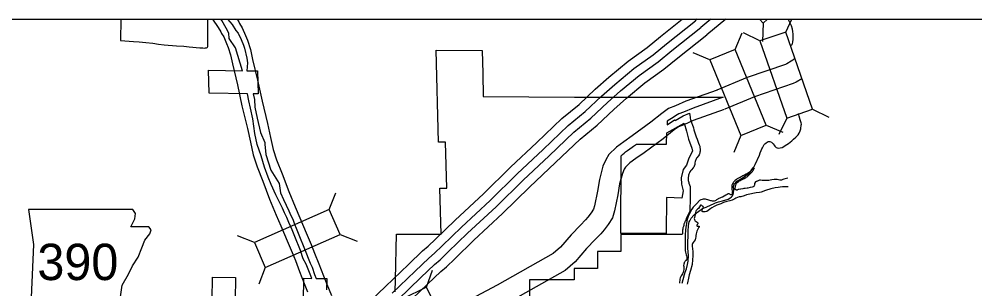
# Model space of a CAD drawing. Extents: x 813775 to 1157140, y 1757555 to 1979907.
# Drawn here: x 848124 to 875936, y 1960976 to 1968812 of the extents above; entities that cross this region are included whole.
import ezdxf

# ---------------------------------------------------------------- set-up
doc = ezdxf.new("R2010")
doc.units = 0
for name, color, linetype in [('Level 10', 7, 'Continuous'), ('Level 15', 7, 'Continuous'), ('Level 19', 7, 'Continuous'), ('Level 2', 7, 'Continuous'), ('Level 20', 7, 'Continuous'), ('Level 21', 7, 'Continuous'), ('Level 6', 7, 'Continuous'), ('Level 9', 7, 'Continuous'), ('R_Draft', 7, 'Continuous')]:
    doc.layers.add(name, color=color, linetype=linetype)

msp = doc.modelspace()

# ---------------------------------------------------------------- linework, layer by layer
at = {"layer": 'Level 10'}
for points in [[(853750, 1968812), (853918, 1968573), (853993, 1968441), (854017, 1968395), (854078, 1968293), (854156, 1968104), (854207, 1967988), (854273, 1967776), (854333, 1967509), (854476, 1966904), (854609, 1966293), (854765, 1965639), (854857, 1965237), (854938, 1964869), (855048, 1964519), (855217, 1964105), (855409, 1963581), (855603, 1963118), (855744, 1962806), (855919, 1962374), (856067, 1962036), (856164, 1961796), (856283, 1961484), (856420, 1961131), (856520, 1960886)], [(854472, 1968812), (854520, 1968729), (854541, 1968688), (854615, 1968564), (854709, 1968339), (854770, 1968197), (854853, 1967931), (854918, 1967644), (855061, 1967036), (855194, 1966427), (855349, 1965776), (855443, 1965369), (855519, 1965023), (855613, 1964723), (855777, 1964322), (855968, 1963800), (856153, 1963357), (856296, 1963042), (856472, 1962607), (856619, 1962269), (856723, 1962016), (856843, 1961700), (856978, 1961353), (857074, 1961117), (857217, 1960783)]]:
    msp.add_lwpolyline(points, dxfattribs=at)
at = {"layer": 'Level 15'}
for points in [[(870696, 1967677), (870635, 1967623), (870591, 1967593), (870459, 1967512), (870423, 1967496), (869313, 1967112), (868427, 1966748)], [(870896, 1967077), (870740, 1966981), (870644, 1966938), (869525, 1966551), (868655, 1966193)], [(868440, 1966753), (867520, 1966426), (867228, 1966298), (867020, 1966212), (866826, 1966072), (866504, 1965815), (865962, 1965419), (865723, 1965251), (865505, 1965097), (865284, 1964878), (865201, 1964726), (865112, 1964537), (865010, 1964152), (864952, 1963814), (864870, 1963384), (864842, 1963294), (864774, 1963189), (864677, 1963062), (864607, 1962978), (864457, 1962827), (864187, 1962549), (863881, 1962183), (863666, 1962003), (862035, 1961085), (861101, 1960587)], [(868641, 1966188), (867741, 1965868), (867462, 1965745), (867313, 1965684), (867188, 1965594), (866868, 1965339), (866311, 1964931), (866069, 1964761), (865892, 1964636), (865768, 1964512), (865735, 1964454), (865678, 1964331), (865597, 1964025), (865543, 1963708), (865453, 1963238), (865390, 1963037), (865265, 1962843), (865147, 1962689), (865052, 1962574), (864885, 1962407), (864633, 1962147), (864307, 1961757), (864009, 1961507), (862324, 1960559)]]:
    msp.add_lwpolyline(points, dxfattribs=at)
at = {"layer": 'Level 19'}
for points in [[(858372, 1960650), (858787, 1961047), (859454, 1961687), (859862, 1962078), (860030, 1962216), (860243, 1962424), (860809, 1962973), (861641, 1963740), (862426, 1964512), (863186, 1965224), (863916, 1965925), (864416, 1966335), (864889, 1966777), (865281, 1967124), (865846, 1967591), (866403, 1967991), (866792, 1968307), (867420, 1968812)], [(858977, 1960848), (859645, 1961489), (860045, 1961872), (860213, 1962011), (860435, 1962227), (860998, 1962773), (861830, 1963541), (862617, 1964314), (863375, 1965025), (864098, 1965720), (864597, 1966128), (865074, 1966573), (865460, 1966915), (866014, 1967373), (866570, 1967772), (866965, 1968094), (867802, 1968766)], [(859150, 1960668), (859818, 1961308), (860211, 1961685), (860380, 1961824), (860610, 1962048), (861170, 1962592), (862003, 1963360), (862790, 1964133), (863547, 1964843), (864264, 1965532), (864761, 1965939), (865242, 1966388), (865623, 1966725), (866167, 1967175), (866722, 1967574), (867122, 1967899), (867959, 1968571)], [(867858, 1968812), (867801, 1968765)], [(868255, 1968812), (867959, 1968571)], [(868691, 1968812), (868133, 1968358)], [(859341, 1960469), (860008, 1961110), (860393, 1961479), (860564, 1961619), (860801, 1961851), (861359, 1962392), (862192, 1963161), (862980, 1963935), (863736, 1964644), (864447, 1965327), (864943, 1965732), (865427, 1966185), (865802, 1966516), (866335, 1966957), (866889, 1967355), (867295, 1967685), (868131, 1968356)]]:
    msp.add_lwpolyline(points, dxfattribs=at)
at = {"layer": 'Level 2'}
for points in [[(870559, 1968058), (870573, 1968059), (870583, 1968059), (870599, 1968065), (870607, 1968069), (870623, 1968089), (870627, 1968099), (870635, 1968157), (870644, 1968225), (870650, 1968303), (870649, 1968371), (870639, 1968451), (870624, 1968517), (870596, 1968615), (870565, 1968696), (870523, 1968772), (870501, 1968812)], [(867616, 1962870), (867626, 1962926), (867640, 1962954), (867658, 1962994), (867683, 1963031), (867755, 1963121), (867799, 1963153), (867907, 1963234), (868012, 1963308), (868112, 1963351), (868258, 1963416), (868328, 1963448), (868384, 1963474), (868478, 1963507), (868592, 1963530), (868692, 1963558), (868752, 1963585), (868804, 1963613), (868856, 1963649), (868880, 1963679), (868903, 1963715), (868911, 1963756), (868915, 1963784), (868919, 1963830), (868920, 1963879), (868916, 1963927), (868916, 1963941), (868916, 1963955), (868918, 1963969), (868934, 1964013), (868959, 1964046), (868979, 1964068), (869013, 1964104), (869047, 1964126), (869077, 1964146), (869191, 1964213), (869269, 1964267), (869307, 1964286), (869360, 1964332), (869438, 1964418), (869500, 1964509), (869545, 1964589), (869668, 1964861), (869687, 1964931), (869715, 1964994), (869739, 1965046), (869752, 1965074), (869778, 1965116), (869808, 1965166), (869828, 1965194), (869852, 1965210), (869906, 1965247), (869932, 1965259), (869970, 1965257), (870020, 1965237), (870062, 1965192), (870093, 1965148), (870117, 1965118), (870157, 1965082), (870183, 1965072), (870213, 1965063), (870274, 1965069), (870324, 1965085), (870377, 1965114), (870419, 1965136), (870509, 1965200), (870563, 1965241), (870605, 1965277), (870659, 1965323), (870726, 1965385), (870792, 1965454), (870820, 1965496), (870836, 1965522), (870854, 1965564), (870871, 1965622), (870873, 1965634), (870883, 1965732), (870886, 1965760), (870878, 1965796), (870853, 1965886), (870825, 1965990), (870800, 1966072)], [(867420, 1961146), (867446, 1961246), (867487, 1961392), (867507, 1961460), (867540, 1961559), (867570, 1961681), (867589, 1961781), (867604, 1961949), (867587, 1962155), (867580, 1962264), (867580, 1962354), (867591, 1962500), (867592, 1962554), (867596, 1962662), (867603, 1962796), (867616, 1962870)]]:
    msp.add_lwpolyline(points, dxfattribs=at)
at = {"layer": 'Level 20'}
for p, q in [((869776, 1968695), (869751, 1968167)), ((870430, 1968438), (870612, 1968812)), ((868958, 1967926), (869161, 1968413)), ((869682, 1968179), (869207, 1968410)), ((868225, 1967625), (867738, 1967829)), ((871207, 1966193), (871682, 1965962)), ((870459, 1965934), (870228, 1965459)), ((869861, 1965728), (870348, 1965525)), ((869128, 1965428), (868925, 1964940)), ((857147, 1963278), (857339, 1963770)), ((854971, 1962325), (854479, 1962518)), ((857465, 1962553), (857956, 1962360)), ((855288, 1961600), (855096, 1961108)), ((859981, 1961024), (860155, 1961522))]:
    msp.add_line(p, q, dxfattribs=at)
msp.add_lwpolyline([(869669, 1968812), (869776, 1968695), (869904, 1968812)], dxfattribs=at)
for points in [[(871207, 1966193), (870430, 1968438), (869682, 1968179), (870459, 1965934)], [(869861, 1965728), (868958, 1967926), (868225, 1967625), (869128, 1965428)], [(855288, 1961600), (857465, 1962553), (857147, 1963278), (854971, 1962325)], [(861014, 1958884), (859981, 1961024), (859268, 1960679), (860301, 1958540)]]:
    msp.add_lwpolyline(points, close=True, dxfattribs=at)
at = {"layer": 'Level 21'}
msp.add_lwpolyline([(848394, 1963283), (848546, 1962268), (848479, 1960728), (848614, 1960644), (848868, 1960644), (848868, 1960102), (851000, 1960102), (851101, 1960322), (851067, 1960677), (851118, 1961083), (851304, 1961405), (851422, 1961642), (851592, 1961896), (851693, 1962166), (851778, 1962386), (851930, 1962572), (851964, 1962691), (851896, 1962775), (851372, 1962775), (851490, 1963012), (851507, 1963164), (851437, 1963281)], close=True, dxfattribs=at)
at = {"layer": 'Level 6'}
for points in [[(851081, 1968812), (851077, 1968188), (851456, 1968162), (851616, 1968150), (851809, 1968135), (852016, 1968109), (852182, 1968087), (852345, 1968070), (852704, 1968041), (852913, 1968023), (853074, 1968008), (853378, 1967981), (853472, 1967974), (853514, 1967972), (853552, 1967976), (853577, 1967981), (853592, 1967988), (853605, 1968000), (853614, 1968014)], [(853614, 1968014), (853619, 1968812)], [(854770, 1966642), (853653, 1966657), (853633, 1967327), (854627, 1967313), (854425, 1967977), (854234, 1968251), (854223, 1968402), (854151, 1968554), (854019, 1968768), (853990, 1968812)], [(854190, 1968812), (854321, 1968660), (854430, 1968484), (854495, 1968400), (854586, 1968224), (854653, 1968054), (854679, 1967964), (854748, 1967681), (854773, 1967543), (854750, 1967311), (855060, 1967307), (855081, 1966638), (854931, 1966640), (854971, 1966474), (854987, 1966255), (855054, 1965938), (855147, 1965522), (855272, 1965227), (855274, 1965175), (855299, 1964880), (855446, 1964421), (855692, 1964037), (855727, 1963769), (855817, 1963572), (855972, 1963240), (856032, 1963106), (856085, 1962996), (856133, 1962851), (856181, 1962740), (856262, 1962543), (856424, 1962137), (856592, 1961727), (856650, 1961608), (856724, 1961397), (856771, 1961279)], [(859063, 1960888), (859073, 1961248), (859108, 1962568), (860402, 1962566), (860366, 1963902), (860566, 1963901), (860531, 1965236), (860331, 1965237), (860260, 1967910), (861601, 1967897), (861613, 1967230), (861625, 1966564), (864281, 1966544), (865654, 1966543), (866986, 1966542)], [(856386, 1959963), (856413, 1961283), (856640, 1961280), (856612, 1961353), (856474, 1961698), (856390, 1961852), (856313, 1962092), (856151, 1962498), (856071, 1962693), (856024, 1962802), (855974, 1962907), (855910, 1963049), (855849, 1963184), (855784, 1963323), (855590, 1963708), (855454, 1964008), (855369, 1964220), (855266, 1964513), (855165, 1964840), (855055, 1965173), (854986, 1965486), (854927, 1965911), (854859, 1966228), (854805, 1966437), (854770, 1966642)], [(866986, 1966542), (868610, 1966541), (867743, 1966221), (867458, 1966112), (867324, 1966056), (867274, 1966032), (867226, 1966005), (867184, 1965978), (866981, 1965843), (866980, 1965741), (867192, 1965889), (867210, 1965865), (867448, 1966002), (867636, 1966078), (867643, 1966011), (867647, 1965974), (867652, 1965947), (867655, 1965931), (867665, 1965893), (867672, 1965865), (867697, 1965783), (867706, 1965756), (867745, 1965650), (867762, 1965596), (867806, 1965451), (867827, 1965392), (867853, 1965323), (867895, 1965213), (867915, 1965159), (867928, 1965118), (867937, 1965079), (867942, 1965038), (867944, 1965009), (867942, 1964974), (867937, 1964946), (867931, 1964921), (867922, 1964896), (867910, 1964871), (867889, 1964837), (867847, 1964785), (867836, 1964769), (867826, 1964752), (867815, 1964725), (867807, 1964701), (867799, 1964673), (867791, 1964636), (867783, 1964581), (867779, 1964566), (867769, 1964537), (867756, 1964515), (867743, 1964496), (867691, 1964438), (867671, 1964414), (867644, 1964374), (867631, 1964351), (867622, 1964330), (867612, 1964305), (867605, 1964281), (867599, 1964245), (867597, 1964222), (867595, 1964153), (867597, 1964120), (867602, 1964094), (867608, 1964070), (867615, 1964047), (867648, 1963945), (867651, 1963921), (867651, 1963629), (867644, 1963220)], [(866955, 1962587), (865638, 1962589), (865647, 1964844), (865682, 1964877), (865732, 1964921), (865773, 1964955), (865831, 1964998), (865959, 1965090), (866003, 1965121), (866085, 1965176), (866967, 1965175), (866970, 1965505), (867479, 1965787), (867542, 1965553), (867606, 1965329), (867703, 1965062), (867722, 1964974), (867612, 1964775), (867545, 1964569), (867452, 1964446), (867388, 1964205), (867401, 1964018), (867449, 1963826), (867404, 1963613), (866963, 1963628), (866955, 1962587)], [(867644, 1963220), (867636, 1963214), (867630, 1963206), (867616, 1963178), (867584, 1963118), (867556, 1963063), (867538, 1963023), (867526, 1962974), (867521, 1962961), (867506, 1962940), (867497, 1962926), (867494, 1962912), (867486, 1962890), (867479, 1962868), (867470, 1962857), (867467, 1962849), (867462, 1962817), (867458, 1962791), (867448, 1962771), (867441, 1962746), (867434, 1962714), (867428, 1962677), (867426, 1962625), (867423, 1962585), (867421, 1962557)], [(867421, 1962557), (866955, 1962557), (865638, 1962559), (865632, 1962062), (864956, 1962063), (864952, 1961565), (864279, 1961566), (864279, 1961234)], [(853051, 1957356), (853067, 1958679), (853717, 1958676), (853735, 1959997), (853752, 1961319)], [(853752, 1961319), (854417, 1961310), (854408, 1960649)], [(856771, 1961279), (857078, 1961275), (857071, 1960945)], [(864279, 1961234), (862977, 1961238), (862972, 1960575), (862320, 1960577), (862316, 1960246), (861662, 1960249), (861657, 1959918), (860839, 1959921), (860832, 1959425), (860341, 1959428), (860341, 1959438), (860141, 1959439), (860146, 1957913), (858985, 1957950)]]:
    msp.add_lwpolyline(points, dxfattribs=at)
at = {"layer": 'Level 9'}
for points in [[(869462, 1964488), (869444, 1964458), (869430, 1964438), (869420, 1964416), (869404, 1964396), (869398, 1964386), (869392, 1964378), (869378, 1964366), (869348, 1964346), (869308, 1964322), (869280, 1964307), (869235, 1964281), (869207, 1964267), (869187, 1964257), (869157, 1964241), (869133, 1964229), (869101, 1964214), (869079, 1964202), (869053, 1964188), (869023, 1964170), (869001, 1964156), (868969, 1964132), (868955, 1964120), (868937, 1964101), (868915, 1964073), (868901, 1964055), (868887, 1964031), (868868, 1963991), (868866, 1963935), (868868, 1963913), (868868, 1963885), (868868, 1963861), (868875, 1963821), (868879, 1963805), (868879, 1963799), (868877, 1963787), (868873, 1963769), (868869, 1963761), (868871, 1963745), (868871, 1963729), (868865, 1963717), (868859, 1963711), (868853, 1963707), (868845, 1963703), (868835, 1963705), (868831, 1963709), (868819, 1963717), (868809, 1963725), (868787, 1963739), (868777, 1963741), (868759, 1963735), (868731, 1963722), (868685, 1963696), (868639, 1963666), (868587, 1963640), (868553, 1963627), (868515, 1963613), (868489, 1963601), (868469, 1963589), (868453, 1963581), (868420, 1963559), (868400, 1963547), (868374, 1963536), (868346, 1963528), (868301, 1963528), (868271, 1963530), (868249, 1963534), (868167, 1963561), (868125, 1963573), (868093, 1963581), (868065, 1963586), (868031, 1963580), (868003, 1963574), (867957, 1963560), (867919, 1963542), (867843, 1963457), (867813, 1963425), (867773, 1963387), (867738, 1963349), (867702, 1963296), (867648, 1963202), (867593, 1963080), (867571, 1963016), (867554, 1962954), (867542, 1962864), (867523, 1962766), (867515, 1962680), (867514, 1962648), (867508, 1962572), (867508, 1962512), (867505, 1962450), (867505, 1962368), (867506, 1962266), (867507, 1962132), (867505, 1962086), (867511, 1962044), (867520, 1962000), (867532, 1961966), (867546, 1961934), (867554, 1961900), (867556, 1961879)], [(869217, 1963887), (869179, 1963883), (869129, 1963873), (869115, 1963873), (869069, 1963866), (869047, 1963858), (869031, 1963850), (869017, 1963844), (868997, 1963846), (868985, 1963850), (868983, 1963850), (868963, 1963864), (868957, 1963882), (868956, 1963920), (868966, 1963940), (868970, 1963956), (868972, 1963968), (868982, 1964002), (868990, 1964020), (869002, 1964042), (869012, 1964058), (869023, 1964066), (869053, 1964092), (869065, 1964102), (869103, 1964126), (869135, 1964141), (869163, 1964155), (869203, 1964177), (869219, 1964185), (869269, 1964213), (869281, 1964221), (869305, 1964234), (869339, 1964262), (869365, 1964288), (869373, 1964296), (869389, 1964310), (869403, 1964326), (869426, 1964346), (869448, 1964368), (869464, 1964388), (869474, 1964405), (869480, 1964415), (869492, 1964431), (869502, 1964455), (869508, 1964467), (869520, 1964487)], [(870491, 1964192), (870420, 1964174), (870380, 1964162), (870346, 1964150), (870306, 1964138), (870257, 1964135), (870219, 1964141), (870181, 1964151), (870153, 1964155), (870131, 1964153), (870097, 1964152), (870031, 1964144), (869981, 1964136), (869941, 1964128), (869895, 1964123), (869845, 1964123), (869803, 1964121), (869749, 1964126), (869696, 1964130), (869666, 1964130), (869634, 1964116), (869610, 1964106), (869590, 1964103), (869578, 1964095), (869564, 1964087), (869556, 1964081), (869527, 1964039), (869525, 1964027), (869523, 1964009), (869519, 1963987), (869515, 1963969), (869507, 1963955), (869499, 1963949), (869481, 1963943), (869451, 1963933), (869399, 1963922), (869331, 1963906), (869311, 1963904), (869255, 1963890), (869217, 1963887)], [(870500, 1963943), (870459, 1963941), (870337, 1963938), (870269, 1963930), (870207, 1963917), (870125, 1963913), (869997, 1963884), (869845, 1963831), (869719, 1963786), (869667, 1963778), (869570, 1963762), (869520, 1963753), (869386, 1963730), (869294, 1963704), (869218, 1963679), (869126, 1963651)], [(869126, 1963651), (869076, 1963647), (869032, 1963634), (868980, 1963610), (868952, 1963592), (868916, 1963568), (868872, 1963555), (868804, 1963533), (868722, 1963513), (868620, 1963482), (868540, 1963449), (868483, 1963423), (868427, 1963403), (868351, 1963368), (868285, 1963330), (868251, 1963310), (868131, 1963223), (868089, 1963211), (868053, 1963213), (868035, 1963211), (868019, 1963214), (868001, 1963222), (867997, 1963234), (867999, 1963254), (868001, 1963268), (868008, 1963290), (868014, 1963306), (868022, 1963322), (868026, 1963340), (868034, 1963354), (868032, 1963370), (868020, 1963372), (868014, 1963380), (868004, 1963388), (867988, 1963396), (867972, 1963404), (867956, 1963404), (867944, 1963398), (867938, 1963392), (867922, 1963360), (867890, 1963314), (867866, 1963293), (867846, 1963275), (867828, 1963255), (867816, 1963237), (867807, 1963199), (867803, 1963155), (867797, 1963125), (867789, 1963095), (867776, 1963047), (867772, 1963017), (867776, 1962989), (867786, 1962957), (867810, 1962947), (867828, 1962933), (867854, 1962916), (867869, 1962908), (867877, 1962894), (867879, 1962886), (867875, 1962864), (867853, 1962842), (867853, 1962838), (867847, 1962824), (867849, 1962810), (867853, 1962802), (867867, 1962798), (867891, 1962798), (867901, 1962798), (867911, 1962798), (867917, 1962790), (867916, 1962772), (867898, 1962750), (867872, 1962710), (867846, 1962648), (867823, 1962574), (867817, 1962526), (867813, 1962490), (867809, 1962448), (867798, 1962398), (867770, 1962357), (867734, 1962321), (867716, 1962291), (867712, 1962263), (867709, 1962221), (867723, 1962137), (867728, 1962063), (867730, 1961936), (867721, 1961820), (867710, 1961688), (867657, 1961509), (867620, 1961379), (867598, 1961289), (867571, 1961153), (867563, 1961116)], [(867556, 1961879), (867555, 1961861), (867551, 1961845), (867541, 1961828), (867527, 1961804), (867509, 1961784), (867495, 1961764), (867481, 1961744), (867473, 1961722), (867462, 1961690), (867460, 1961658), (867464, 1961626), (867468, 1961596), (867470, 1961568), (867469, 1961536), (867459, 1961500), (867447, 1961460), (867427, 1961410), (867411, 1961386), (867393, 1961358), (867364, 1961292), (867354, 1961258), (867352, 1961238), (867345, 1961162), (867344, 1961145)]]:
    msp.add_lwpolyline(points, dxfattribs=at)
at = {"layer": 'R_Draft'}
msp.add_lwpolyline([(823472, 1968812), (896470, 1968812), (896470, 1905247), (823472, 1905247)], close=True, dxfattribs=at)
msp.add_lwpolyline([(823472, 1968812), (896470, 1968812), (896470, 1905247), (823472, 1905247)], close=True, dxfattribs=at)

# ---------------------------------------------------------------- texts
at = {"layer": 'Level 21'}
msp.add_text('390', height=1056, dxfattribs=at).set_placement((848655, 1961231))

doc.saveas('drawing.dxf')
